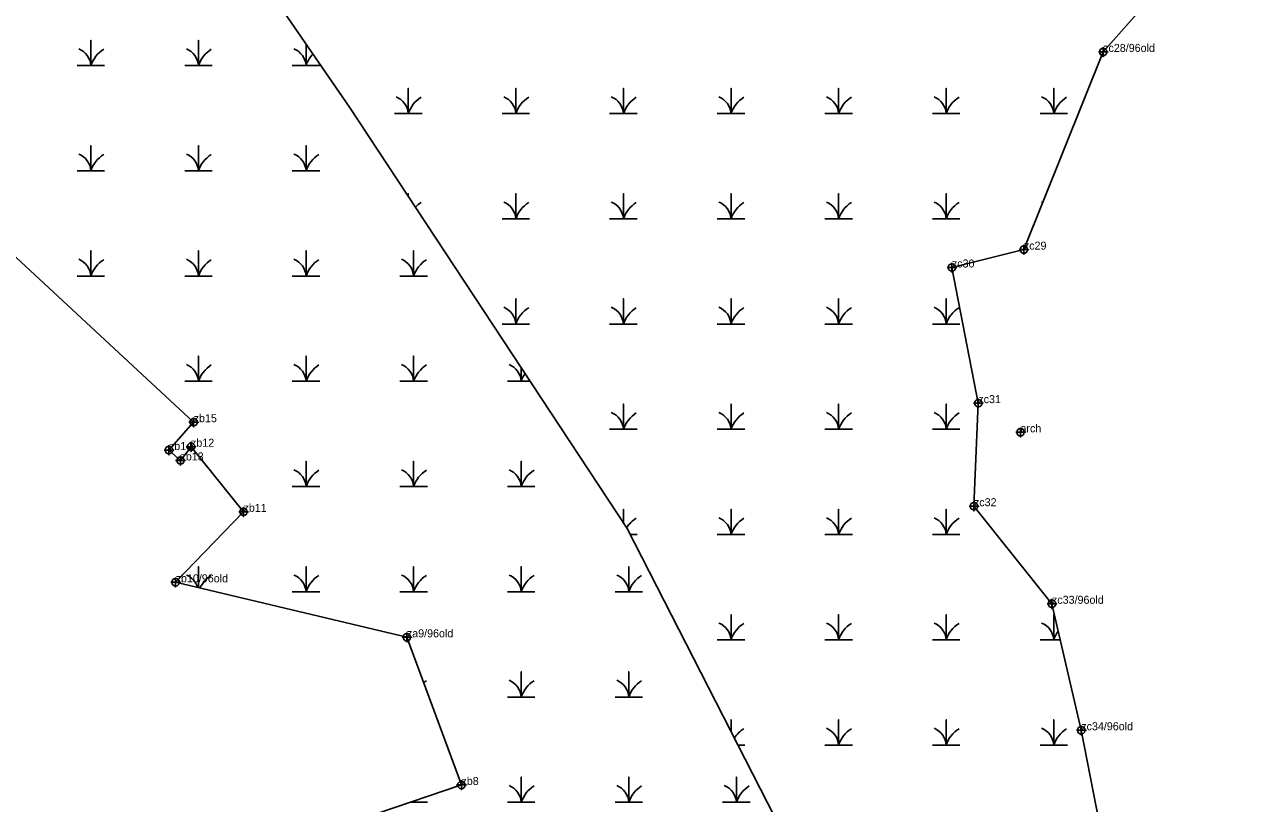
# Model space of a CAD drawing. Extents: x 2071991 to 2268989, y 436479 to 469629.
# Drawn here: x 2251993 to 2252753, y 438188 to 438675 of the extents above; entities that cross this region are included whole.
import ezdxf

# ---------------------------------------------------------------- set-up
doc = ezdxf.new("R2010")
doc.units = 0
for name, color, linetype in [('Exist Environmental Wetland Boundary', 7, 'Continuous'), ('Exist Environmental Wetland Boundary Cogo Comment', 7, 'Continuous'), ('Exist Environmental Wetland Boundary Cogo Point CELL', 7, 'Continuous'), ('Exist Hydro Jurisdictional Stream or Body of Water NEU Mitigable', 7, 'Continuous'), ('Exist Hydro Swamp or Marsh', 7, 'Continuous')]:
    doc.layers.add(name, color=color, linetype=linetype)

msp = doc.modelspace()

# ---------------------------------------------------------------- linework, layer by layer
at = {"layer": 'Exist Environmental Wetland Boundary'}
for points in [[(2251159.61, 439601.08), (2251261.98, 439510.93), (2251353.72, 439431.67), (2251408.06, 439276.46), (2251418.5, 439100.24), (2251356.47, 439015.14), (2251265.14, 438865.12), (2251366.82, 438844.78), (2251385.46, 438875.42), (2251556.91, 438853.1), (2251718.82, 438830.13), (2251868.44, 438639.97), (2251940.74, 438572.89), (2252098.49, 438426.72), (2252083.03, 438409.31), (2252090.25, 438402.8), (2252096.84, 438411.38), (2252129.61, 438370.68)], [(2252702.34, 438698.78), (2252666.6, 438658.16), (2252617.07, 438534.58), (2252572.12, 438523.42), (2252588.63, 438438.61), (2252585.9, 438374.2), (2252634.63, 438313.22), (2252652.92, 438234.16), (2252675.4, 438119.23), (2252680.55, 438043.34), (2252745.58, 437967.01), (2252753.12, 437963.41)], [(2252129.61, 438370.68), (2252087.24, 438326.64), (2252231.67, 438292.27), (2252265.76, 438199.96), (2252213.02, 438182.13), (2252209.12, 438152.05), (2252210.2, 438134.32), (2252276.43, 438157.85), (2252330.72, 438053.7), (2252370.68, 437902.26), (2252366.64, 437873.55), (2252367.26, 437851.27), (2252370.7, 437841.48)]]:
    msp.add_lwpolyline(points, dxfattribs=at)
at = {"layer": 'Exist Environmental Wetland Boundary Cogo Point CELL'}
for points in [[(2252666.6, 438661.16), (2252666.6, 438655.16), (2252666.6, 438658.16), (2252669.6, 438658.16), (2252663.6, 438658.16)], [(2252617.07, 438537.58), (2252617.07, 438531.58), (2252617.07, 438534.58), (2252620.07, 438534.58), (2252614.07, 438534.58)], [(2252572.12, 438526.42), (2252572.12, 438520.42), (2252572.12, 438523.42), (2252575.12, 438523.42), (2252569.12, 438523.42)], [(2252588.63, 438441.61), (2252588.63, 438435.61), (2252588.63, 438438.61), (2252591.63, 438438.61), (2252585.63, 438438.61)], [(2252098.49, 438429.72), (2252098.49, 438423.72), (2252098.49, 438426.72), (2252101.49, 438426.72), (2252095.49, 438426.72)], [(2252614.96, 438423.41), (2252614.96, 438417.41), (2252614.96, 438420.41), (2252617.96, 438420.41), (2252611.96, 438420.41)], [(2252083.03, 438412.31), (2252083.03, 438406.31), (2252083.03, 438409.31), (2252086.03, 438409.31), (2252080.03, 438409.31)], [(2252096.84, 438414.38), (2252096.84, 438408.38), (2252096.84, 438411.38), (2252099.84, 438411.38), (2252093.84, 438411.38)], [(2252090.25, 438405.8), (2252090.25, 438399.8), (2252090.25, 438402.8), (2252093.25, 438402.8), (2252087.25, 438402.8)], [(2252129.61, 438373.68), (2252129.61, 438367.68), (2252129.61, 438370.68), (2252132.61, 438370.68), (2252126.61, 438370.68)], [(2252585.9, 438377.2), (2252585.9, 438371.2), (2252585.9, 438374.2), (2252588.9, 438374.2), (2252582.9, 438374.2)], [(2252087.24, 438329.64), (2252087.24, 438323.64), (2252087.24, 438326.64), (2252090.24, 438326.64), (2252084.24, 438326.64)], [(2252634.63, 438316.22), (2252634.63, 438310.22), (2252634.63, 438313.22), (2252637.63, 438313.22), (2252631.63, 438313.22)], [(2252231.67, 438295.27), (2252231.67, 438289.27), (2252231.67, 438292.27), (2252234.67, 438292.27), (2252228.67, 438292.27)], [(2252652.92, 438237.16), (2252652.92, 438231.16), (2252652.92, 438234.16), (2252655.92, 438234.16), (2252649.92, 438234.16)], [(2252265.76, 438202.96), (2252265.76, 438196.96), (2252265.76, 438199.96), (2252268.76, 438199.96), (2252262.76, 438199.96)]]:
    msp.add_lwpolyline(points, dxfattribs=at)
for centre in [(2252666.6, 438658.16), (2252617.07, 438534.58), (2252572.12, 438523.42), (2252588.63, 438438.61), (2252098.49, 438426.72), (2252614.96, 438420.41), (2252083.03, 438409.31), (2252096.84, 438411.38), (2252090.25, 438402.8), (2252129.61, 438370.68), (2252585.9, 438374.2), (2252087.24, 438326.64), (2252634.63, 438313.22), (2252231.67, 438292.27), (2252652.92, 438234.16), (2252265.76, 438199.96)]:
    msp.add_circle(centre, 2.34, dxfattribs=at)
at = {"layer": 'Exist Hydro Jurisdictional Stream or Body of Water NEU Mitigable'}
for p, q in [((2252009.78, 438893.45), (2252195.92, 438623.67)), ((2252195.92, 438623.67), (2252369.23, 438360.31)), ((2252369.23, 438360.31), (2252510.45, 438084.11))]:
    msp.add_line(p, q, dxfattribs=at)
at = {"layer": 'Exist Hydro Swamp or Marsh'}
for p, q in [((2252371.19, 438356.49), (2252375.55, 438356.49)), ((2252438.45, 438224.92), (2252442.76, 438224.92))]:
    msp.add_line(p, q, dxfattribs=at)
for points in [[(2252025.69, 438649.62), (2252034.3, 438649.62), (2252034.3, 438665.4), (2252034.3, 438649.62), (2252042.9, 438649.62)], [(2252092.9, 438649.62), (2252101.5, 438649.62), (2252101.5, 438665.4), (2252101.5, 438649.62), (2252110.1, 438649.62)], [(2252160.1, 438649.62), (2252168.7, 438649.62), (2252168.7, 438663.12)], [(2252168.7, 438663.12), (2252168.7, 438649.62), (2252177.3, 438649.62)], [(2252223.94, 438619.61), (2252232.55, 438619.61), (2252232.55, 438635.39), (2252232.55, 438619.61), (2252241.15, 438619.61)], [(2252291.15, 438619.61), (2252299.75, 438619.61), (2252299.75, 438635.39), (2252299.75, 438619.61), (2252308.35, 438619.61)], [(2252358.35, 438619.61), (2252366.95, 438619.61), (2252366.95, 438635.39), (2252366.95, 438619.61), (2252375.55, 438619.61)], [(2252425.55, 438619.61), (2252434.16, 438619.61), (2252434.16, 438635.39), (2252434.16, 438619.61), (2252442.76, 438619.61)], [(2252492.76, 438619.61), (2252501.36, 438619.61), (2252501.36, 438635.39), (2252501.36, 438619.61), (2252509.96, 438619.61)], [(2252559.96, 438619.61), (2252568.56, 438619.61), (2252568.56, 438635.39), (2252568.56, 438619.61), (2252577.16, 438619.61)], [(2252627.16, 438619.61), (2252635.76, 438619.61), (2252635.76, 438635.39), (2252635.76, 438619.61), (2252644.37, 438619.61)], [(2252025.69, 438583.84), (2252034.3, 438583.84), (2252034.3, 438599.62), (2252034.3, 438583.84), (2252042.9, 438583.84)], [(2252092.9, 438583.84), (2252101.5, 438583.84), (2252101.5, 438599.62), (2252101.5, 438583.84), (2252110.1, 438583.84)], [(2252160.1, 438583.84), (2252168.7, 438583.84), (2252168.7, 438599.62), (2252168.7, 438583.84), (2252177.3, 438583.84)], [(2252232.55, 438568.02), (2252232.55, 438569.61), (2252232.55, 438568.02)], [(2252291.15, 438553.83), (2252299.75, 438553.83), (2252299.75, 438569.61), (2252299.75, 438553.83), (2252308.35, 438553.83)], [(2252358.35, 438553.83), (2252366.95, 438553.83), (2252366.95, 438569.61), (2252366.95, 438553.83), (2252375.55, 438553.83)], [(2252425.55, 438553.83), (2252434.16, 438553.83), (2252434.16, 438569.61), (2252434.16, 438553.83), (2252442.76, 438553.83)], [(2252492.76, 438553.83), (2252501.36, 438553.83), (2252501.36, 438569.61), (2252501.36, 438553.83), (2252509.96, 438553.83)], [(2252559.96, 438553.83), (2252568.56, 438553.83), (2252568.56, 438569.61), (2252568.56, 438553.83), (2252577.16, 438553.83)], [(2252025.69, 438518.06), (2252034.3, 438518.06), (2252034.3, 438533.84), (2252034.3, 438518.06), (2252042.9, 438518.06)], [(2252092.9, 438518.06), (2252101.5, 438518.06), (2252101.5, 438533.84), (2252101.5, 438518.06), (2252110.1, 438518.06)], [(2252160.1, 438518.06), (2252168.7, 438518.06), (2252168.7, 438533.84), (2252168.7, 438518.06), (2252177.3, 438518.06)], [(2252227.3, 438518.06), (2252235.91, 438518.06), (2252235.91, 438533.84), (2252235.91, 438518.06), (2252244.51, 438518.06)], [(2252291.15, 438488.05), (2252299.75, 438488.05), (2252299.75, 438503.83), (2252299.75, 438488.05), (2252308.35, 438488.05)], [(2252358.35, 438488.05), (2252366.95, 438488.05), (2252366.95, 438503.83), (2252366.95, 438488.05), (2252375.55, 438488.05)], [(2252425.55, 438488.05), (2252434.16, 438488.05), (2252434.16, 438503.83), (2252434.16, 438488.05), (2252442.76, 438488.05)], [(2252492.76, 438488.05), (2252501.36, 438488.05), (2252501.36, 438503.83), (2252501.36, 438488.05), (2252509.96, 438488.05)], [(2252559.96, 438488.05), (2252568.56, 438488.05), (2252568.56, 438503.83), (2252568.56, 438488.05), (2252577.16, 438488.05)], [(2252092.9, 438452.28), (2252101.5, 438452.28), (2252101.5, 438468.06), (2252101.5, 438452.28), (2252110.1, 438452.28)], [(2252160.1, 438452.28), (2252168.7, 438452.28), (2252168.7, 438468.06), (2252168.7, 438452.28), (2252177.3, 438452.28)], [(2252227.3, 438452.28), (2252235.91, 438452.28), (2252235.91, 438468.06), (2252235.91, 438452.28), (2252244.51, 438452.28)], [(2252294.51, 438452.28), (2252303.11, 438452.28), (2252303.11, 438460.79)], [(2252303.11, 438460.79), (2252303.11, 438452.28), (2252308.71, 438452.28)], [(2252358.35, 438422.27), (2252366.95, 438422.27), (2252366.95, 438438.05), (2252366.95, 438422.27), (2252375.55, 438422.27)], [(2252425.55, 438422.27), (2252434.16, 438422.27), (2252434.16, 438438.05), (2252434.16, 438422.27), (2252442.76, 438422.27)], [(2252492.76, 438422.27), (2252501.36, 438422.27), (2252501.36, 438438.05), (2252501.36, 438422.27), (2252509.96, 438422.27)], [(2252559.96, 438422.27), (2252568.56, 438422.27), (2252568.56, 438438.05), (2252568.56, 438422.27), (2252577.16, 438422.27)], [(2252160.1, 438386.5), (2252168.7, 438386.5), (2252168.7, 438402.28), (2252168.7, 438386.5), (2252177.3, 438386.5)], [(2252227.3, 438386.5), (2252235.91, 438386.5), (2252235.91, 438402.28), (2252235.91, 438386.5), (2252244.51, 438386.5)], [(2252294.51, 438386.5), (2252303.11, 438386.5), (2252303.11, 438402.28), (2252303.11, 438386.5), (2252311.71, 438386.5)], [(2252366.95, 438363.78), (2252366.95, 438372.27), (2252366.95, 438363.78)], [(2252425.55, 438356.49), (2252434.16, 438356.49), (2252434.16, 438372.27), (2252434.16, 438356.49), (2252442.76, 438356.49)], [(2252492.76, 438356.49), (2252501.36, 438356.49), (2252501.36, 438372.27), (2252501.36, 438356.49), (2252509.96, 438356.49)], [(2252559.96, 438356.49), (2252568.56, 438356.49), (2252568.56, 438372.27), (2252568.56, 438356.49), (2252577.16, 438356.49)], [(2252101.5, 438323.24), (2252101.5, 438336.5), (2252101.5, 438323.24)], [(2252160.1, 438320.72), (2252168.7, 438320.72), (2252168.7, 438336.5), (2252168.7, 438320.72), (2252177.3, 438320.72)], [(2252227.3, 438320.72), (2252235.91, 438320.72), (2252235.91, 438336.5), (2252235.91, 438320.72), (2252244.51, 438320.72)], [(2252294.51, 438320.72), (2252303.11, 438320.72), (2252303.11, 438336.5), (2252303.11, 438320.72), (2252311.71, 438320.72)], [(2252361.71, 438320.72), (2252370.31, 438320.72), (2252370.31, 438336.5), (2252370.31, 438320.72), (2252378.91, 438320.72)], [(2252425.55, 438290.71), (2252434.16, 438290.71), (2252434.16, 438306.49), (2252434.16, 438290.71), (2252442.76, 438290.71)], [(2252492.76, 438290.71), (2252501.36, 438290.71), (2252501.36, 438306.49), (2252501.36, 438290.71), (2252509.96, 438290.71)], [(2252559.96, 438290.71), (2252568.56, 438290.71), (2252568.56, 438306.49), (2252568.56, 438290.71), (2252577.16, 438290.71)], [(2252627.16, 438290.71), (2252635.76, 438290.71), (2252635.76, 438306.49), (2252635.76, 438290.71), (2252639.84, 438290.71)], [(2252294.51, 438254.94), (2252303.11, 438254.94), (2252303.11, 438270.72), (2252303.11, 438254.94), (2252311.71, 438254.94)], [(2252361.71, 438254.94), (2252370.31, 438254.94), (2252370.31, 438270.72), (2252370.31, 438254.94), (2252378.91, 438254.94)], [(2252434.16, 438233.33), (2252434.16, 438240.71), (2252434.16, 438233.33)], [(2252492.76, 438224.92), (2252501.36, 438224.92), (2252501.36, 438240.71), (2252501.36, 438224.92), (2252509.96, 438224.92)], [(2252559.96, 438224.92), (2252568.56, 438224.92), (2252568.56, 438240.71), (2252568.56, 438224.92), (2252577.16, 438224.92)], [(2252627.16, 438224.92), (2252635.76, 438224.92), (2252635.76, 438240.71), (2252635.76, 438224.92), (2252644.37, 438224.92)], [(2252294.51, 438189.16), (2252303.11, 438189.16), (2252303.11, 438204.94), (2252303.11, 438189.16), (2252311.71, 438189.16)], [(2252361.71, 438189.16), (2252370.31, 438189.16), (2252370.31, 438204.94), (2252370.31, 438189.16), (2252378.91, 438189.16)], [(2252428.91, 438189.16), (2252437.52, 438189.16), (2252437.52, 438204.94), (2252437.52, 438189.16), (2252446.12, 438189.16)], [(2252233.81, 438189.16), (2252235.91, 438189.16), (2252235.91, 438189.87)], [(2252235.91, 438189.87), (2252235.91, 438189.16), (2252244.51, 438189.16)]]:
    msp.add_lwpolyline(points, dxfattribs=at)
for centre, radius, start, end in [((2252022.03, 438648.74), 12.3, 4.14034, 67.53497), ((2252052.54, 438643.56), 19.22, 122.12745, 161.62219), ((2252089.23, 438648.74), 12.3, 4.14034, 67.53497), ((2252119.74, 438643.56), 19.22, 122.12745, 161.62219), ((2252156.44, 438648.74), 12.3, 4.14034, 67.53497), ((2252186.94, 438643.56), 19.22, 136.3379, 161.62219), ((2252220.28, 438618.72), 12.3, 4.14034, 67.53497), ((2252250.79, 438613.55), 19.22, 122.12745, 161.62219), ((2252287.48, 438618.72), 12.3, 4.14034, 67.53497), ((2252317.99, 438613.55), 19.22, 122.12745, 161.62219), ((2252354.69, 438618.72), 12.3, 4.14034, 67.53497), ((2252385.19, 438613.55), 19.22, 122.12745, 161.62219), ((2252421.89, 438618.72), 12.3, 4.14034, 67.53497), ((2252452.4, 438613.55), 19.22, 122.12745, 161.62219), ((2252489.09, 438618.72), 12.3, 4.14034, 67.53497), ((2252519.6, 438613.55), 19.22, 122.12745, 161.62219), ((2252556.3, 438618.72), 12.3, 4.14034, 67.53497), ((2252586.8, 438613.55), 19.22, 122.12745, 161.62219), ((2252623.5, 438618.72), 12.3, 4.14034, 67.53497), ((2252654.01, 438613.55), 19.22, 122.12745, 161.62219), ((2252022.03, 438582.96), 12.3, 4.14034, 67.53497), ((2252052.54, 438577.78), 19.22, 122.12745, 161.62219), ((2252089.23, 438582.96), 12.3, 4.14034, 67.53497), ((2252119.74, 438577.78), 19.22, 122.12745, 161.62219), ((2252156.44, 438582.96), 12.3, 4.14034, 67.53497), ((2252186.94, 438577.78), 19.22, 122.12745, 161.62219), ((2252250.79, 438547.77), 19.22, 122.12745, 135.68075), ((2252287.48, 438552.94), 12.3, 4.14034, 67.53497), ((2252317.99, 438547.77), 19.22, 122.12745, 161.62219), ((2252354.69, 438552.94), 12.3, 4.14034, 67.53497), ((2252385.19, 438547.77), 19.22, 122.12745, 161.62219), ((2252421.89, 438552.94), 12.3, 4.14034, 67.53497), ((2252452.4, 438547.77), 19.22, 122.12745, 161.62219), ((2252489.09, 438552.94), 12.3, 4.14034, 67.53497), ((2252519.6, 438547.77), 19.22, 122.12745, 161.62219), ((2252556.3, 438552.94), 12.3, 4.14034, 67.53497), ((2252586.8, 438547.77), 19.22, 122.12745, 161.62219), ((2252623.5, 438552.94), 12.3, 64.13302, 67.53497), ((2252022.03, 438517.18), 12.3, 4.14034, 67.53497), ((2252052.54, 438512), 19.22, 122.12745, 161.62219), ((2252089.23, 438517.18), 12.3, 4.14034, 67.53497), ((2252119.74, 438512), 19.22, 122.12745, 161.62219), ((2252156.44, 438517.18), 12.3, 4.14034, 67.53497), ((2252186.94, 438512), 19.22, 122.12745, 161.62219), ((2252223.64, 438517.18), 12.3, 4.14034, 67.53497), ((2252254.15, 438512), 19.22, 122.12745, 161.62219), ((2252287.48, 438487.16), 12.3, 4.14034, 67.53497), ((2252317.99, 438481.99), 19.22, 122.12745, 161.62219), ((2252354.69, 438487.16), 12.3, 4.14034, 67.53497), ((2252385.19, 438481.99), 19.22, 122.12745, 161.62219), ((2252421.89, 438487.16), 12.3, 4.14034, 67.53497), ((2252452.4, 438481.99), 19.22, 122.12745, 161.62219), ((2252489.09, 438487.16), 12.3, 4.14034, 67.53497), ((2252519.6, 438481.99), 19.22, 122.12745, 161.62219), ((2252556.3, 438487.16), 12.3, 4.14034, 67.53497), ((2252586.8, 438481.99), 19.22, 122.12745, 161.62219), ((2252089.23, 438451.39), 12.3, 4.14034, 67.53497), ((2252119.74, 438446.22), 19.22, 122.12745, 161.62219), ((2252156.44, 438451.39), 12.3, 4.14034, 67.53497), ((2252186.94, 438446.22), 19.22, 122.12745, 161.62219), ((2252223.64, 438451.39), 12.3, 4.14034, 67.53497), ((2252254.15, 438446.22), 19.22, 122.12745, 161.62219), ((2252290.84, 438451.39), 12.3, 4.14034, 67.53497), ((2252321.35, 438446.22), 19.22, 145.43727, 161.62219), ((2252354.69, 438421.38), 12.3, 4.14034, 67.53497), ((2252385.19, 438416.21), 19.22, 122.12745, 161.62219), ((2252421.89, 438421.38), 12.3, 4.14034, 67.53497), ((2252452.4, 438416.21), 19.22, 122.12745, 161.62219), ((2252489.09, 438421.38), 12.3, 4.14034, 67.53497), ((2252519.6, 438416.21), 19.22, 122.12745, 161.62219), ((2252556.3, 438421.38), 12.3, 4.14034, 67.53497), ((2252586.8, 438416.21), 19.22, 122.12745, 161.62219), ((2252119.74, 438380.44), 19.22, 122.12745, 124.16966), ((2252156.44, 438385.61), 12.3, 4.14034, 67.53497), ((2252186.94, 438380.44), 19.22, 122.12745, 161.62219), ((2252223.64, 438385.61), 12.3, 4.14034, 67.53497), ((2252254.15, 438380.44), 19.22, 122.12745, 161.62219), ((2252290.84, 438385.61), 12.3, 4.14034, 67.53497), ((2252321.35, 438380.44), 19.22, 122.12745, 161.62219), ((2252385.19, 438350.43), 19.22, 122.12745, 147.60706), ((2252421.89, 438355.6), 12.3, 4.14034, 67.53497), ((2252452.4, 438350.43), 19.22, 122.12745, 161.62219), ((2252489.09, 438355.6), 12.3, 4.14034, 67.53497), ((2252519.6, 438350.43), 19.22, 122.12745, 161.62219), ((2252556.3, 438355.6), 12.3, 4.14034, 67.53497), ((2252586.8, 438350.43), 19.22, 122.12745, 161.62219), ((2252089.23, 438319.83), 12.3, 16.66398, 67.53497), ((2252119.74, 438314.66), 19.22, 122.12745, 154.21469), ((2252156.44, 438319.83), 12.3, 4.14034, 67.53497), ((2252186.94, 438314.66), 19.22, 122.12745, 161.62219), ((2252223.64, 438319.83), 12.3, 4.14034, 67.53497), ((2252254.15, 438314.66), 19.22, 122.12745, 161.62219), ((2252290.84, 438319.83), 12.3, 4.14034, 67.53497), ((2252321.35, 438314.66), 19.22, 122.12745, 161.62219), ((2252358.05, 438319.83), 12.3, 4.14034, 67.53497), ((2252388.55, 438314.66), 19.22, 122.12745, 161.62219), ((2252421.89, 438289.82), 12.3, 4.14034, 67.53497), ((2252452.4, 438284.64), 19.22, 122.12745, 161.62219), ((2252489.09, 438289.82), 12.3, 4.14034, 67.53497), ((2252519.6, 438284.64), 19.22, 122.12745, 161.62219), ((2252556.3, 438289.82), 12.3, 4.14034, 67.53497), ((2252586.8, 438284.64), 19.22, 122.12745, 161.62219), ((2252623.5, 438289.82), 12.3, 4.14034, 67.53497), ((2252654.01, 438284.64), 19.22, 143.34984, 161.62219), ((2252254.15, 438248.88), 19.22, 122.12745, 128.61687), ((2252290.84, 438254.05), 12.3, 4.14034, 67.53497), ((2252321.35, 438248.88), 19.22, 122.12745, 161.62219), ((2252358.05, 438254.05), 12.3, 4.14034, 67.53497), ((2252388.55, 438248.88), 19.22, 122.12745, 161.62219), ((2252452.4, 438218.86), 19.22, 122.12745, 147.23489), ((2252489.09, 438224.04), 12.3, 4.14034, 67.53497), ((2252519.6, 438218.86), 19.22, 122.12745, 161.62219), ((2252556.3, 438224.04), 12.3, 4.14034, 67.53497), ((2252586.8, 438218.86), 19.22, 122.12745, 161.62219), ((2252623.5, 438224.04), 12.3, 4.14034, 67.53497), ((2252654.01, 438218.86), 19.22, 122.12745, 161.62219), ((2252290.84, 438188.27), 12.3, 4.14034, 67.53497), ((2252321.35, 438183.1), 19.22, 122.12745, 161.62219), ((2252358.05, 438188.27), 12.3, 4.14034, 67.53497), ((2252388.55, 438183.1), 19.22, 122.12745, 161.62219), ((2252425.25, 438188.27), 12.3, 4.14034, 67.53497), ((2252455.76, 438183.1), 19.22, 122.12745, 161.62219), ((2252223.64, 438188.27), 12.3, 4.14034, 7.3443), ((2252254.15, 438183.1), 19.22, 159.0756, 161.62219)]:
    msp.add_arc(centre, radius, start, end, dxfattribs=at)

# ---------------------------------------------------------------- texts
at = {"layer": 'Exist Environmental Wetland Boundary Cogo Comment'}
for s, p in [('zc28/96old', (2252666.6, 438658.16)), ('zc29', (2252617.07, 438534.58)), ('zc30', (2252572.12, 438523.42)), ('zc31', (2252588.63, 438438.61)), ('zb15', (2252098.49, 438426.72)), ('arch', (2252614.96, 438420.41)), ('zb12', (2252096.84, 438411.38)), ('zb14', (2252083.03, 438409.31)), ('zb13', (2252090.25, 438402.8)), ('zc32', (2252585.9, 438374.2)), ('zb11', (2252129.61, 438370.68)), ('zb10/96old', (2252087.24, 438326.64)), ('zc33/96old', (2252634.63, 438313.22)), ('za9/96old', (2252231.67, 438292.27)), ('zc34/96old', (2252652.92, 438234.16)), ('zb8', (2252265.76, 438199.96))]:
    msp.add_text(s, height=5, dxfattribs=at).set_placement(p)

doc.saveas('drawing.dxf')
